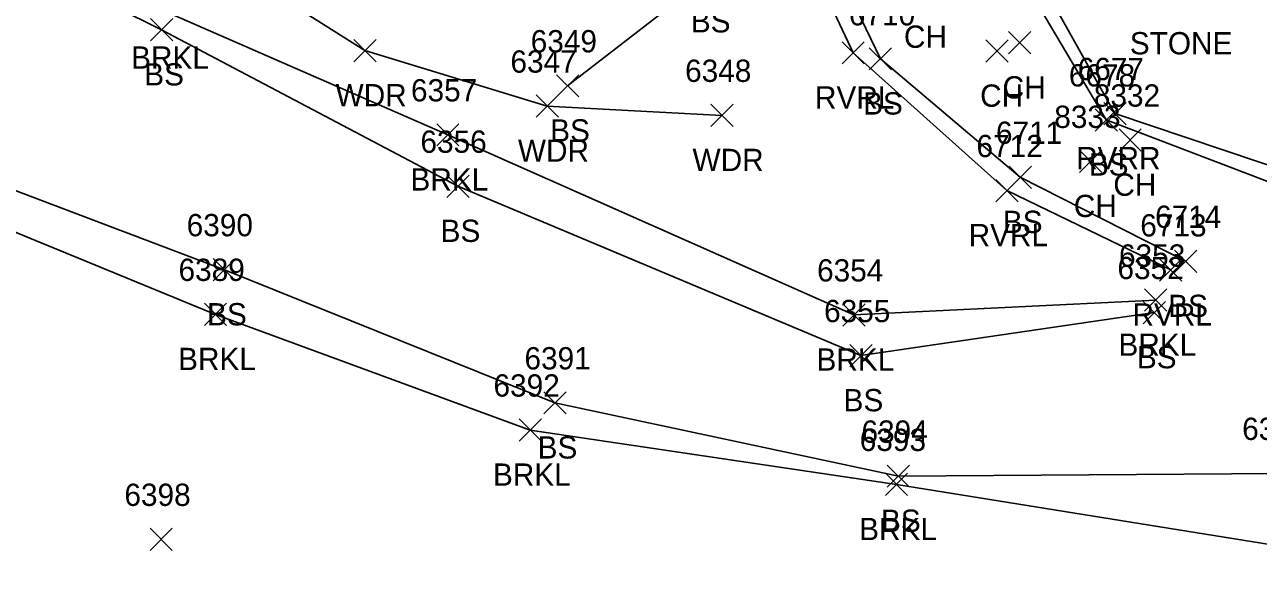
# Model space of a CAD drawing. Extents: x 1588028 to 1589597, y 137576 to 138176.
# Drawn here: x 1588875.5 to 1588986.3, y 137778.1 to 137826.6 of the extents above; entities that cross this region are included whole.
import ezdxf

# ---------------------------------------------------------------- set-up
doc = ezdxf.new("R2010")
doc.units = 0
for name, color, linetype in [('L_A', 7, 'Continuous'), ('L_I', 7, 'Continuous'), ('L_TIC', 7, 'Continuous'), ('LAWA', 7, 'Continuous'), ('LAWE', 7, 'Continuous'), ('LELB', 7, 'Continuous')]:
    doc.layers.add(name, color=color, linetype=linetype)

msp = doc.modelspace()

# ---------------------------------------------------------------- linework, layer by layer
at = {"layer": 'L_TIC'}
for points in [[(1588886.83, 137825.14), (1588888.83, 137827.14)], [(1588888.83, 137825.14), (1588886.83, 137827.14)], [(1588905.09, 137823.27), (1588907.09, 137825.27)], [(1588907.09, 137823.27), (1588905.09, 137825.27)], [(1588948.92, 137823.07), (1588950.92, 137825.07)], [(1588950.92, 137823.07), (1588948.92, 137825.07)], [(1588961.83, 137823.23), (1588963.83, 137825.23)], [(1588963.83, 137823.23), (1588961.83, 137825.23)], [(1588963.86, 137823.97), (1588965.86, 137825.97)], [(1588965.86, 137823.97), (1588963.86, 137825.97)], [(1588951.37, 137822.53), (1588953.37, 137824.53)], [(1588953.37, 137822.53), (1588951.37, 137824.53)], [(1588923.28, 137820.11), (1588925.28, 137822.11)], [(1588925.28, 137820.11), (1588923.28, 137822.11)], [(1588921.46, 137818.29), (1588923.46, 137820.29)], [(1588923.46, 137818.29), (1588921.46, 137820.29)], [(1588972.43, 137817.62), (1588974.43, 137819.62)], [(1588974.43, 137817.62), (1588972.43, 137819.62)], [(1588937.14, 137817.46), (1588939.14, 137819.46)], [(1588939.14, 137817.46), (1588937.14, 137819.46)], [(1588971.64, 137817.05), (1588973.64, 137819.05)], [(1588973.64, 137817.05), (1588971.64, 137819.05)], [(1588912.53, 137815.71), (1588914.53, 137817.71)], [(1588914.53, 137815.71), (1588912.53, 137817.71)], [(1588973.79, 137815.24), (1588975.79, 137817.24)], [(1588975.79, 137815.24), (1588973.79, 137817.24)], [(1588970.24, 137813.33), (1588972.24, 137815.33)], [(1588972.24, 137813.33), (1588970.24, 137815.33)], [(1588913.44, 137811.1), (1588915.44, 137813.1)], [(1588915.44, 137811.1), (1588913.44, 137813.1)], [(1588963.92, 137811.9), (1588965.92, 137813.9)], [(1588965.92, 137811.9), (1588963.92, 137813.9)], [(1588962.73, 137810.71), (1588964.73, 137812.71)], [(1588964.73, 137810.71), (1588962.73, 137812.71)], [(1588978.77, 137804.36), (1588980.77, 137806.36)], [(1588980.77, 137804.36), (1588978.77, 137806.36)], [(1588892.47, 137803.61), (1588894.47, 137805.61)], [(1588894.47, 137803.61), (1588892.47, 137805.61)], [(1588977.44, 137803.59), (1588979.44, 137805.59)], [(1588979.44, 137803.59), (1588977.44, 137805.59)], [(1588976.09, 137800.88), (1588978.09, 137802.88)], [(1588978.09, 137800.88), (1588976.09, 137802.88)], [(1588975.95, 137799.76), (1588977.95, 137801.76)], [(1588977.95, 137799.76), (1588975.95, 137801.76)], [(1588891.67, 137799.6), (1588893.67, 137801.6)], [(1588893.67, 137799.6), (1588891.67, 137801.6)], [(1588948.99, 137799.55), (1588950.99, 137801.55)], [(1588950.99, 137799.55), (1588948.99, 137801.55)], [(1588949.62, 137795.9), (1588951.62, 137797.9)], [(1588951.62, 137795.9), (1588949.62, 137797.9)], [(1588922.15, 137791.66), (1588924.15, 137793.66)], [(1588924.15, 137791.66), (1588922.15, 137793.66)], [(1588919.93, 137789.22), (1588921.93, 137791.22)], [(1588921.93, 137789.22), (1588919.93, 137791.22)], [(1588952.81, 137784.34), (1588954.81, 137786.34)], [(1588954.81, 137784.34), (1588952.81, 137786.34)], [(1588952.98, 137785.08), (1588954.98, 137787.08)], [(1588954.98, 137785.08), (1588952.98, 137787.08)], [(1588886.79, 137779.41), (1588888.79, 137781.41)], [(1588888.79, 137779.41), (1588886.79, 137781.41)]]:
    msp.add_lwpolyline(points, dxfattribs=at)
at = {"layer": 'LAWA'}
msp.add_lwpolyline([(1588886.81, 137836.46), (1588906.09, 137824.27), (1588922.46, 137819.29), (1588938.14, 137818.46)], dxfattribs=at)
at = {"layer": 'LAWE'}
for points in [[(1588977.09, 137801.88), (1588949.99, 137800.55), (1588913.53, 137816.71), (1588888.44, 137827.65), (1588864.1, 137841.15), (1588838.93, 137847.71), (1588814.53, 137847.16), (1588788.4, 137846.57), (1588760.06, 137845.85), (1588744.31, 137852.31), (1588711.69, 137843.68)], [(1588941.88, 137841.17), (1588949.92, 137824.07), (1588963.73, 137811.71), (1588978.44, 137804.59)], [(1588965.44, 137832.87), (1588973.43, 137818.62), (1588989.6, 137813.18), (1589022.84, 137804.12), (1589064.64, 137785.89), (1589085.42, 137779.69), (1589097.72, 137781.17), (1589112.63, 137775.03), (1589131.45, 137759.72), (1589147.93, 137745.25), (1589161.35, 137734.82)], [(1588713.41, 137823.71), (1588738.42, 137825.5), (1588767.27, 137826.98), (1588799.24, 137826.53), (1588827.86, 137827.03), (1588853.9, 137816.5), (1588892.67, 137800.6), (1588920.93, 137790.22), (1588953.81, 137785.34), (1588994.96, 137778.72)]]:
    msp.add_lwpolyline(points, dxfattribs=at)
at = {"layer": 'LELB'}
for points in [[(1588976.95, 137800.76), (1588950.62, 137796.9), (1588914.44, 137812.1), (1588887.83, 137826.14), (1588862.59, 137838.68), (1588839.41, 137844.48), (1588814.28, 137844.58), (1588790.42, 137844.54), (1588761.5, 137843.62), (1588744.06, 137845.91), (1588711.1, 137839.15), (1588710.72, 137829.12), (1588738.02, 137826.67), (1588767.07, 137829.2), (1588800.85, 137829.84), (1588826.76, 137827.94), (1588856.44, 137818.62), (1588893.47, 137804.61), (1588923.15, 137792.66), (1588953.98, 137786.08), (1588988.16, 137786.33)], [(1588943.17, 137842.61), (1588952.37, 137823.53), (1588964.92, 137812.9), (1588979.77, 137805.36)], [(1588924.28, 137821.11), (1588936.9, 137830.9), (1588939.92, 137838.69)], [(1588964.15, 137832.41), (1588972.64, 137818.05), (1588989.97, 137811.45)]]:
    msp.add_lwpolyline(points, dxfattribs=at)

# ---------------------------------------------------------------- texts
at = {"layer": 'L_A'}
for s, p in [('BS', (1588935.34, 137825.9)), ('CH', (1588954.48, 137824.52)), ('STONE', (1588974.76, 137823.93)), ('BRKL', (1588885.09, 137822.65)), ('BS', (1588886.27, 137821.14)), ('CH', (1588963.35, 137819.97)), ('WDR', (1588903.45, 137819.27)), ('RVRL', (1588946.49, 137819.07)), ('CH', (1588961.32, 137819.23)), ('BS', (1588950.81, 137818.53)), ('BS', (1588922.72, 137816.11)), ('WDR', (1588919.82, 137814.29)), ('WDR', (1588935.5, 137813.46)), ('RVRR', (1588969.94, 137813.62)), ('BS', (1588971.08, 137813.05)), ('BRKL', (1588910.17, 137811.71)), ('CH', (1588973.28, 137811.24)), ('CH', (1588969.73, 137809.33)), ('BS', (1588963.36, 137807.9)), ('BS', (1588912.88, 137807.1)), ('RVRL', (1588960.29, 137806.71)), ('BS', (1588978.21, 137800.36)), ('BS', (1588891.91, 137799.61)), ('RVRL', (1588975, 137799.59)), ('BRKL', (1588973.74, 137796.88)), ('BRKL', (1588889.31, 137795.6)), ('BRKL', (1588946.63, 137795.55)), ('BS', (1588975.39, 137795.76)), ('BS', (1588949.06, 137791.9)), ('BS', (1588921.59, 137787.66)), ('BRKL', (1588917.58, 137785.22)), ('BS', (1588952.42, 137781.08)), ('BRKL', (1588950.46, 137780.34))]:
    msp.add_text(s, height=2, dxfattribs=at).set_placement(p)
at = {"layer": 'L_I'}
for s, p in [('6710', (1588949.54, 137826.53)), ('6349', (1588920.97, 137824.11)), ('6347', (1588919.15, 137822.29)), ('6348', (1588934.83, 137821.46)), ('6678', (1588969.29, 137821.05)), ('6677', (1588970.08, 137821.62)), ('6357', (1588910.22, 137819.71)), ('8332', (1588971.53, 137819.24)), ('8333', (1588967.98, 137817.33)), ('6711', (1588962.74, 137815.9)), ('6356', (1588911.07, 137815.1)), ('6712', (1588960.99, 137814.71)), ('6390', (1588890.08, 137807.61)), ('6713', (1588975.7, 137807.59)), ('6714', (1588977.03, 137808.36)), ('6353', (1588973.79, 137804.88)), ('6389', (1588889.35, 137803.6)), ('6354', (1588946.68, 137803.55)), ('6352', (1588973.65, 137803.76)), ('6355', (1588947.31, 137799.9)), ('6391', (1588920.41, 137795.66)), ('6392', (1588917.63, 137793.22)), ('6394', (1588950.67, 137789.08)), ('6395', (1588984.85, 137789.33)), ('6393', (1588950.51, 137788.34)), ('6398', (1588884.49, 137783.41))]:
    msp.add_text(s, height=2, dxfattribs=at).set_placement(p)

doc.saveas('drawing.dxf')
